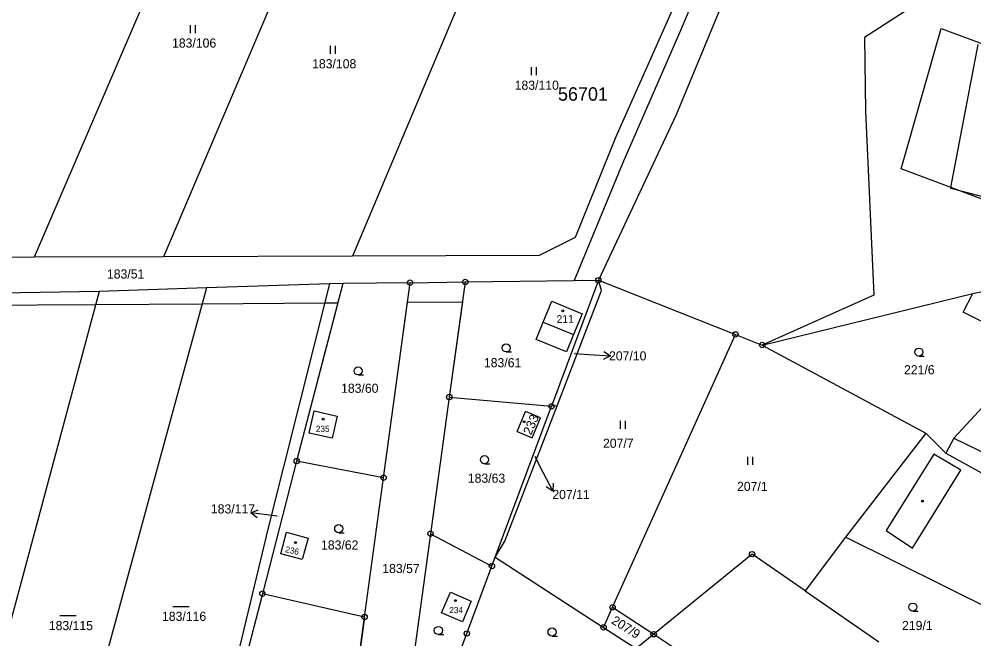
# Model space of a CAD drawing. Extents: x -747333 to -745433, y -1133152 to -1130600.
# Drawn here: x -746813.1 to -746635.6, y -1132147.6 to -1132032.4 of the extents above; entities that cross this region are included whole.
import ezdxf

# ---------------------------------------------------------------- set-up
doc = ezdxf.new("R2010")
doc.units = 0
for name, color, linetype in [('Vrstva 1', 7, 'Continuous'), ('Vrstva 16', 7, 'Continuous'), ('Vrstva 18', 7, 'Continuous'), ('Vrstva 19', 7, 'Continuous'), ('Vrstva 24', 7, 'Continuous'), ('Vrstva 25', 7, 'Continuous'), ('Vrstva 3', 7, 'Continuous'), ('Vrstva 37', 7, 'Continuous'), ('Vrstva 4', 7, 'Continuous'), ('Vrstva 52', 7, 'Continuous'), ('Vrstva 53', 7, 'Continuous'), ('Vrstva 6', 7, 'Continuous')]:
    doc.layers.add(name, color=color, linetype=linetype)

msp = doc.modelspace()

# ---------------------------------------------------------------- linework, layer by layer
at = {"layer": 'Vrstva 1'}
for p, q in [((-746704.8, -1132082.86), (-746705.38, -1132080.91)), ((-746705.38, -1132080.91), (-746679.89, -1132091)), ((-746713.07, -1132104.3), (-746704.8, -1132082.86)), ((-746715.63, -1132088.71), (-746714.06, -1132084.83)), ((-746714.06, -1132084.83), (-746708.4, -1132087.18)), ((-746708.4, -1132087.18), (-746709.98, -1132090.99)), ((-746716.94, -1132091.93), (-746715.63, -1132088.71)), ((-746709.98, -1132090.99), (-746711.32, -1132094.22)), ((-746702.74, -1132141.73), (-746679.89, -1132091)), ((-746679.89, -1132091), (-746674.91, -1132092.97)), ((-746711.32, -1132094.22), (-746716.94, -1132091.93)), ((-746674.91, -1132092.97), (-746644.51, -1132109.35)), ((-746722.76, -1132129.43), (-746713.07, -1132104.3)), ((-746713.07, -1132104.3), (-746714.1, -1132104.36)), ((-746644.51, -1132109.35), (-746659.43, -1132128.69)), ((-746644.51, -1132109.35), (-746640.76, -1132113.05)), ((-746724.55, -1132132.39), (-746722.76, -1132129.43)), ((-746659.43, -1132128.69), (-746666.94, -1132138.69)), ((-746625.72, -1132145.44), (-746659.43, -1132128.69)), ((-746676.81, -1132131.86), (-746695.1, -1132146.75)), ((-746666.94, -1132138.69), (-746676.81, -1132131.86)), ((-746724.55, -1132132.39), (-746704.42, -1132145.46)), ((-746666.94, -1132138.69), (-746653.23, -1132148.18)), ((-746704.42, -1132145.46), (-746702.74, -1132141.73)), ((-746702.74, -1132141.73), (-746695.1, -1132146.75)), ((-746704.42, -1132145.46), (-746698.35, -1132149.4)), ((-746695.1, -1132146.75), (-746698.35, -1132149.4)), ((-746695.1, -1132146.75), (-746643.87, -1132180.43))]:
    msp.add_line(p, q, dxfattribs=at)
for points in [[(-746646.39, -1131931.6), (-746690.31, -1132034.95)], [(-746596.68, -1131997.54), (-746655.89, -1132035.79)], [(-746687.61, -1132021.59), (-746692.88, -1132033.52)], [(-746692.88, -1132033.52), (-746702.16, -1132054.24)], [(-746649.06, -1132060.2), (-746641.62, -1132034.15)], [(-746641.62, -1132034.15), (-746598.91, -1132049.91)], [(-746690.31, -1132034.95), (-746700.88, -1132059.24)], [(-746655.89, -1132035.79), (-746655.72, -1132049.5)], [(-746655.72, -1132049.5), (-746654.17, -1132083.68)], [(-746702.16, -1132054.24), (-746709.72, -1132073.01)], [(-746700.88, -1132059.24), (-746709.89, -1132080.97)], [(-746606.74, -1132076.1), (-746649.06, -1132060.2)], [(-746709.72, -1132073.01), (-746716.38, -1132076.31)], [(-746810.33, -1132076.62), (-746837.35, -1132076.92)], [(-746786.25, -1132076.55), (-746810.33, -1132076.62)], [(-746751.09, -1132076.46), (-746786.25, -1132076.55)], [(-746716.38, -1132076.31), (-746751.09, -1132076.46)], [(-746635.72, -1132083.37), (-746615.53, -1132079.14)], [(-746755.32, -1132081.61), (-746778.25, -1132082.36)], [(-746752.93, -1132081.53), (-746761.49, -1132114.56)], [(-746752.93, -1132081.53), (-746755.32, -1132081.61)], [(-746740.4, -1132081.38), (-746752.93, -1132081.53)], [(-746745.32, -1132117.64), (-746740.4, -1132081.38)], [(-746740.4, -1132081.38), (-746730.14, -1132081.25)], [(-746730.14, -1132081.25), (-746733.1, -1132102.66)], [(-746730.14, -1132081.25), (-746709.89, -1132080.97)], [(-746705.38, -1132080.91), (-746714.1, -1132104.36)], [(-746709.89, -1132080.97), (-746705.38, -1132080.91)], [(-746798.2, -1132083.02), (-746820.24, -1132083.39)], [(-746778.25, -1132082.36), (-746798.2, -1132083.02)], [(-746674.91, -1132092.97), (-746635.72, -1132083.37)], [(-746654.17, -1132083.68), (-746674.91, -1132092.97)], [(-746637.54, -1132086.86), (-746635.72, -1132083.37)], [(-746623.94, -1132093.67), (-746637.54, -1132086.86)], [(-746623.94, -1132093.67), (-746639.26, -1132110.3)], [(-746733.1, -1132102.66), (-746736.6, -1132128.06)], [(-746733.1, -1132102.66), (-746714.1, -1132104.36)], [(-746759.16, -1132109.33), (-746758.21, -1132105.23)], [(-746758.21, -1132105.23), (-746753.94, -1132106.19)], [(-746724.55, -1132132.39), (-746714.1, -1132104.36)], [(-746720.5, -1132109.04), (-746717.68, -1132110.21), (-746716.14, -1132106.48), (-746718.96, -1132105.32)], [(-746720.5, -1132109.04), (-746718.96, -1132105.32)], [(-746753.94, -1132106.19), (-746754.88, -1132110.32)], [(-746754.88, -1132110.32), (-746759.16, -1132109.33)], [(-746639.26, -1132110.3), (-746640.76, -1132113.05)], [(-746639.26, -1132110.3), (-746615.65, -1132121.76)], [(-746640.76, -1132113.05), (-746617.06, -1132126.14)], [(-746761.49, -1132114.56), (-746767.86, -1132139.21)], [(-746745.32, -1132117.64), (-746761.49, -1132114.56)], [(-746748.85, -1132143.55), (-746745.32, -1132117.64)], [(-746764.45, -1132131.77), (-746763.36, -1132127.77)], [(-746763.36, -1132127.77), (-746759.36, -1132128.86)], [(-746736.6, -1132128.06), (-746743.8, -1132180.44)], [(-746736.6, -1132128.06), (-746725.17, -1132134.06)], [(-746759.36, -1132128.86), (-746760.45, -1132132.87)], [(-746760.45, -1132132.87), (-746764.45, -1132131.77)], [(-746725.17, -1132134.06), (-746724.55, -1132132.39)], [(-746729.85, -1132146.61), (-746725.17, -1132134.06)], [(-746734.55, -1132142.77), (-746732.9, -1132138.91)], [(-746732.9, -1132138.91), (-746729.03, -1132140.57)], [(-746767.86, -1132139.21), (-746773.98, -1132162.83)], [(-746748.85, -1132143.55), (-746767.86, -1132139.21)], [(-746729.03, -1132140.57), (-746730.68, -1132144.42)], [(-746748.85, -1132143.55), (-746752.17, -1132167.89)], [(-746730.68, -1132144.42), (-746734.55, -1132142.77)], [(-746741.45, -1132177.74), (-746729.85, -1132146.61)]]:
    msp.add_lwpolyline(points, dxfattribs=at)
at = {"layer": 'Vrstva 16'}
for p, q in [((-746704.392779, -1132094.15748), (-746703.150501, -1132094.999646)), ((-746713.77739, -1132118.638645), (-746713.834575, -1132120.138388)), ((-746768.824847, -1132125.070803), (-746770.015712, -1132124.15738))]:
    msp.add_line(p, q, dxfattribs=at)
for points in [[(-746709.8, -1132094.52), (-746707.14, -1132094.71)], [(-746707.14, -1132094.71), (-746703.150501, -1132094.999646), (-746704.501397, -1132095.653542)], [(-746717.22, -1132113.7), (-746715.7, -1132116.6)], [(-746715.7, -1132116.6), (-746713.834575, -1132120.138388), (-746715.104286, -1132119.338179)], [(-746766.05, -1132124.68), (-746770.015712, -1132124.15738), (-746768.628864, -1132123.583661)], [(-746765.15, -1132124.8), (-746766.05, -1132124.68)]]:
    msp.add_lwpolyline(points, dxfattribs=at)
at = {"layer": 'Vrstva 24'}
for p, q in [((-746740.45, -1132081.38), (-746740.35, -1132081.38)), ((-746730.19, -1132081.25), (-746730.09, -1132081.25)), ((-746705.43, -1132080.91), (-746705.33, -1132080.91)), ((-746679.94, -1132091), (-746679.84, -1132091)), ((-746674.96, -1132092.97), (-746674.86, -1132092.97)), ((-746733.15, -1132102.66), (-746733.05, -1132102.66)), ((-746714.15, -1132104.36), (-746714.05, -1132104.36)), ((-746761.54, -1132114.56), (-746761.44, -1132114.56)), ((-746745.37, -1132117.64), (-746745.27, -1132117.64)), ((-746736.65, -1132128.06), (-746736.55, -1132128.06)), ((-746676.86, -1132131.86), (-746676.76, -1132131.86)), ((-746725.22, -1132134.06), (-746725.12, -1132134.06)), ((-746767.91, -1132139.21), (-746767.81, -1132139.21)), ((-746702.79, -1132141.73), (-746702.69, -1132141.73)), ((-746748.9, -1132143.55), (-746748.8, -1132143.55)), ((-746704.47, -1132145.46), (-746704.37, -1132145.46)), ((-746729.9, -1132146.61), (-746729.8, -1132146.61)), ((-746695.15, -1132146.75), (-746695.05, -1132146.75))]:
    msp.add_line(p, q, dxfattribs=at)
for centre in [(-746705.38, -1132080.91), (-746740.4, -1132081.38), (-746730.14, -1132081.25), (-746679.89, -1132091), (-746674.91, -1132092.97), (-746733.1, -1132102.66), (-746714.1, -1132104.36), (-746761.49, -1132114.56), (-746745.32, -1132117.64), (-746736.6, -1132128.06), (-746676.81, -1132131.86), (-746725.17, -1132134.06), (-746767.86, -1132139.21), (-746702.74, -1132141.73), (-746748.85, -1132143.55), (-746729.85, -1132146.61), (-746704.42, -1132145.46), (-746695.1, -1132146.75)]:
    msp.add_circle(centre, 0.499289, dxfattribs=at)
at = {"layer": 'Vrstva 25'}
for p, q in [((-746781.31, -1132033.48), (-746781.31, -1132034.98)), ((-746780.31, -1132034.98), (-746780.31, -1132033.48)), ((-746755.24, -1132037.33), (-746755.24, -1132038.83)), ((-746754.24, -1132038.83), (-746754.24, -1132037.33)), ((-746717.9, -1132041.32), (-746717.9, -1132042.82)), ((-746716.9, -1132042.82), (-746716.9, -1132041.32)), ((-746722.53, -1132094.25), (-746721.53, -1132094.25)), ((-746645.78, -1132095.04), (-746644.78, -1132095.04)), ((-746750.06, -1132098.54), (-746749.06, -1132098.54)), ((-746701.32, -1132107.06), (-746701.32, -1132108.56)), ((-746700.32, -1132108.56), (-746700.32, -1132107.06)), ((-746677.67, -1132113.75), (-746677.67, -1132115.25)), ((-746676.67, -1132115.25), (-746676.67, -1132113.75)), ((-746726.57, -1132115.04), (-746725.57, -1132115.04)), ((-746753.67, -1132127.87), (-746752.67, -1132127.87)), ((-746784.5, -1132141.56), (-746781.5, -1132141.56)), ((-746646.91, -1132142.44), (-746645.91, -1132142.44)), ((-746805.52, -1132143.28), (-746802.52, -1132143.28)), ((-746735.14, -1132146.8), (-746734.14, -1132146.8)), ((-746714, -1132147.08), (-746713, -1132147.08))]:
    msp.add_line(p, q, dxfattribs=at)
for centre, radius in [((-746712.02, -1132086.62), 0.174503), ((-746722.53, -1132093.5), 0.75), ((-746645.78, -1132094.29), 0.75), ((-746750.06, -1132097.79), 0.75), ((-746756.58, -1132106.77), 0.174503), ((-746719.17, -1132107.23), 0.174503), ((-746726.57, -1132114.29), 0.75), ((-746645.13, -1132121.99), 0.174503), ((-746753.67, -1132127.12), 0.75), ((-746761.7, -1132129.71), 0.174503), ((-746731.94, -1132140.5), 0.174503), ((-746646.91, -1132141.69), 0.75), ((-746735.14, -1132146.05), 0.75), ((-746714, -1132146.33), 0.75)]:
    msp.add_circle(centre, radius, dxfattribs=at)
at = {"layer": 'Vrstva 3'}
for points in [[(-746715.63, -1132088.71), (-746714.06, -1132084.83)], [(-746714.06, -1132084.83), (-746708.4, -1132087.18)], [(-746708.4, -1132087.18), (-746709.98, -1132090.99)], [(-746715.63, -1132088.71), (-746709.98, -1132090.99)], [(-746759.16, -1132109.33), (-746758.21, -1132105.23)], [(-746758.21, -1132105.23), (-746753.94, -1132106.19)], [(-746720.5, -1132109.04), (-746718.96, -1132105.32)], [(-746720.5, -1132109.04), (-746717.68, -1132110.21), (-746716.14, -1132106.48), (-746718.96, -1132105.32)], [(-746753.94, -1132106.19), (-746754.88, -1132110.32)], [(-746754.88, -1132110.32), (-746759.16, -1132109.33)], [(-746764.45, -1132131.77), (-746763.36, -1132127.77)], [(-746763.36, -1132127.77), (-746759.36, -1132128.86)], [(-746759.36, -1132128.86), (-746760.45, -1132132.87)], [(-746760.45, -1132132.87), (-746764.45, -1132131.77)], [(-746734.55, -1132142.77), (-746732.9, -1132138.91)], [(-746732.9, -1132138.91), (-746729.03, -1132140.57)], [(-746729.03, -1132140.57), (-746730.68, -1132144.42)], [(-746730.68, -1132144.42), (-746734.55, -1132142.77)]]:
    msp.add_lwpolyline(points, dxfattribs=at)
at = {"layer": 'Vrstva 37'}
for centre in [(-746712.02, -1132086.62), (-746756.58, -1132106.77), (-746719.17, -1132107.23), (-746761.7, -1132129.71), (-746731.94, -1132140.5)]:
    msp.add_circle(centre, 0.174503, dxfattribs=at)
at = {"layer": 'Vrstva 4'}
msp.add_line((-746715.63, -1132088.71), (-746709.98, -1132090.99), dxfattribs=at)
for points in [[(-746642.98, -1132113.24), (-746651.88, -1132127.45)], [(-746637.99, -1132116.23), (-746642.98, -1132113.24)], [(-746646.97, -1132130.75), (-746637.99, -1132116.23)], [(-746651.88, -1132127.45), (-746646.97, -1132130.75)]]:
    msp.add_lwpolyline(points, dxfattribs=at)
at = {"layer": 'Vrstva 52'}
for points in [[(-746596.5, -1132061.75), (-746599.06, -1132074.5), (-746605.74, -1132072.76), (-746637.93, -1132064.38), (-746639.87, -1132063.87), (-746639.84, -1132063.67), (-746634.75, -1132037.12)], [(-746820.81, -1132085.58), (-746798.85, -1132085.43), (-746779.05, -1132085.29), (-746756.2, -1132085.13), (-746753.86, -1132085.11), (-746761.49, -1132114.56), (-746767.86, -1132139.21), (-746773.98, -1132162.83), (-746778.93, -1132181.95), (-746754.82, -1132187.37), (-746752.17, -1132167.89), (-746748.85, -1132143.55), (-746745.32, -1132117.64), (-746740.89, -1132085.03), (-746730.65, -1132084.95), (-746733.1, -1132102.66), (-746736.6, -1132128.06), (-746743.8, -1132180.44), (-746742.61, -1132180.85), (-746743.19, -1132182.42)]]:
    msp.add_lwpolyline(points, dxfattribs=at)
at = {"layer": 'Vrstva 6'}
for points in [[(-746773.71, -1131991.57), (-746810.33, -1132076.62)], [(-746753.17, -1131998.74), (-746786.25, -1132076.55)], [(-746722.82, -1132009.3), (-746751.09, -1132076.46)], [(-746678.35, -1132019.74), (-746690.91, -1132050.15)], [(-746690.91, -1132050.15), (-746705.38, -1132080.91)], [(-746766.7, -1132126.93), (-746755.32, -1132081.61)], [(-746798.2, -1132083.02), (-746825.13, -1132182.99)], [(-746778.25, -1132082.36), (-746805.63, -1132182.7)], [(-746781.38, -1132187.88), (-746766.7, -1132126.93)]]:
    msp.add_lwpolyline(points, dxfattribs=at)

# ---------------------------------------------------------------- texts
at = {"layer": 'Vrstva 16'}
for s, p in [('207/10', (-746703.4, -1132095.84)), ('207/11', (-746713.95, -1132121.61)), ('183/117', (-746777.441997, -1132124.29))]:
    msp.add_text(s, height=1.7, dxfattribs=at).set_placement(p)
at = {"layer": 'Vrstva 18'}
for s, height, p in [('183/106', 1.7, (-746784.67, -1132037.68)), ('183/108', 1.7, (-746758.62, -1132041.53)), ('183/110', 1.7, (-746720.95, -1132045.52)), ('183/51', 1.7, (-746796.77, -1132080.61)), ('207/10', 0.1, (-746709.8, -1132094.52)), ('183/61', 1.7, (-746726.67, -1132097.11)), ('221/6', 1.7, (-746648.55, -1132098.42)), ('183/60', 1.7, (-746753.23, -1132101.86)), ('207/7', 1.7, (-746704.517742, -1132112.08)), ('207/11', 0.1, (-746717.22, -1132113.7)), ('183/63', 1.7, (-746729.66, -1132118.58)), ('207/1', 1.7, (-746679.6, -1132120.11)), ('183/117', 0.1, (-746765.15, -1132124.8)), ('183/62', 1.7, (-746756.964573, -1132131)), ('183/57', 1.7, (-746745.57, -1132135.37)), ('183/116', 1.7, (-746786.53, -1132144.26)), ('183/115', 1.7, (-746807.58, -1132145.98)), ('219/1', 1.7, (-746648.91, -1132145.97))]:
    msp.add_text(s, height=height, dxfattribs=at).set_placement(p)
msp.add_text('207/9', height=1.7, rotation=327.6, dxfattribs=at).set_placement((-746703.107184, -1132144.616584))
at = {"layer": 'Vrstva 19'}
for s, height, rotation, p in [('211', 1.44, 1.08099, (-746713.138372, -1132088.879593)), ('233', 1.7, 66.38364, (-746717.8997, -1132109.833176)), ('236', 1.14, 348.05583, (-746763.69, -1132131.48))]:
    msp.add_text(s, height=height, rotation=rotation, dxfattribs=at).set_placement(p)
for s, p in [('235', (-746757.92, -1132109.13)), ('234', (-746733.11, -1132142.82))]:
    msp.add_text(s, height=1.14, dxfattribs=at).set_placement(p)
at = {"layer": 'Vrstva 53'}
msp.add_text('56701', height=2.5, dxfattribs=at).set_placement((-746712.898976, -1132047.55))

doc.saveas('drawing.dxf')
